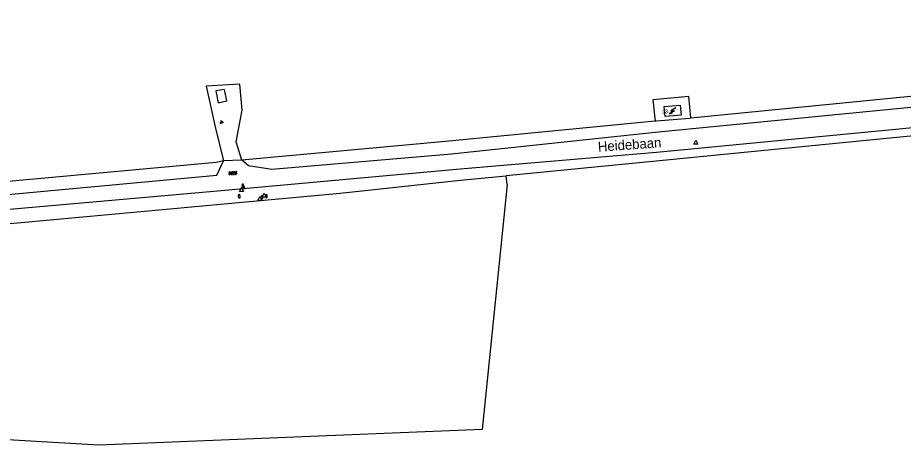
# Model space of a CAD drawing. Extents: x 126000 to 131009, y 393000 to 395500.
# Drawn here: x 127601.7 to 127827.3, y 394615 to 394723.9 of the extents above; entities that cross this region are included whole.
import ezdxf

# ---------------------------------------------------------------- set-up
doc = ezdxf.new("R2010")
doc.units = 0
for name, color, linetype in [('gg-afsc-draadraster', 7, 'Continuous'), ('gg-afsc-faunaraster', 7, 'Continuous'), ('gg-afsc-hekwerk', 7, 'Continuous'), ('gg-anno-huisnummerreeks BGT', 7, 'Continuous'), ('gg-anno-openbare ruimte label', 7, 'Continuous'), ('gg-bbg-hoofdgebouw', 7, 'Continuous'), ('gg-knt-onverhard', 7, 'Continuous'), ('gg-kwrk-betonelement', 7, 'Continuous'), ('gt-grn-groengrens', 7, 'Continuous'), ('gt-symb-brandkraan', 7, 'Continuous'), ('gt-symb-groenvak', 7, 'Continuous'), ('gt-symb-overige verharding', 7, 'Continuous'), ('gt-symb-trafo symbool', 7, 'Continuous'), ('gt-symb-waterafsluiter', 7, 'Continuous')]:
    doc.layers.add(name, color=color, linetype=linetype)

# ---------------------------------------------------------------- blocks, each defined once
blk = doc.blocks.new('gt0-WAFSL')
at = {"layer": 'gt-symb-waterafsluiter'}
for p, q in [((-0.5, -0.33), (0, 0.67)), ((0, 0.67), (0.5, -0.33)), ((0.5, -0.33), (-0.5, -0.33))]:
    blk.add_line(p, q, dxfattribs=at)
blk = doc.blocks.new('gt0-HSP')
at = {"layer": 'gt-symb-trafo symbool'}
for points in [[(0.77, 0.75), (-0.53, 0), (0.47, 0), (-0.83, -0.75)], [(-0.22, -0.24), (-0.83, -0.75), (-0.08, -0.48)]]:
    blk.add_lwpolyline(points, dxfattribs=at)
blk = doc.blocks.new('gt0-BR')
at = {"layer": 'gt-symb-brandkraan'}
for centre, radius, start, end in [((-0.24, 0), 0.206, 107.5669, 252.4331), ((0.6, -2.66), 3, 106.892, 107.5669), ((0, -0.69), 0.938, 73.108, 106.892), ((-0.6, -2.66), 3, 72.4331, 73.108), ((0.24, 0), 0.206, 287.567, 72.4331), ((0.6, 2.66), 3, 252.4331, 253.108), ((0, 0.69), 0.938, 253.108, 286.8921), ((-0.6, 2.66), 3, 286.8921, 287.567)]:
    blk.add_arc(centre, radius, start, end, dxfattribs=at)
blk = doc.blocks.new('gt0-OVH')
at = {"layer": 'gt-symb-overige verharding'}
for points in [[(-0.97, 0.3), (-0.97, 0.31), (-0.96, 0.32), (-0.97, 0.33), (-0.97, 0.34), (-0.98, 0.35), (-0.99, 0.35), (-1, 0.36), (-1.01, 0.35), (-1.02, 0.35), (-1.03, 0.34), (-1.03, 0.33), (-1.04, 0.32), (-1.03, 0.31), (-1.03, 0.3), (-1.02, 0.29), (-1.01, 0.29), (-1, 0.28), (-0.99, 0.29), (-0.98, 0.29)], [(-0.87, 0.11), (-0.87, 0.12), (-0.86, 0.13), (-0.87, 0.14), (-0.87, 0.15), (-0.88, 0.16), (-0.89, 0.16), (-0.9, 0.16), (-0.91, 0.16), (-0.92, 0.16), (-0.93, 0.15), (-0.93, 0.14), (-0.94, 0.13), (-0.93, 0.12), (-0.93, 0.11), (-0.92, 0.1), (-0.91, 0.09), (-0.9, 0.09), (-0.89, 0.09), (-0.88, 0.1)], [(-0.77, 0.3), (-0.77, 0.31), (-0.76, 0.32), (-0.77, 0.33), (-0.77, 0.34), (-0.78, 0.35), (-0.79, 0.35), (-0.8, 0.36), (-0.81, 0.35), (-0.82, 0.35), (-0.83, 0.34), (-0.83, 0.33), (-0.84, 0.32), (-0.83, 0.31), (-0.83, 0.3), (-0.82, 0.29), (-0.81, 0.29), (-0.8, 0.28), (-0.79, 0.29), (-0.78, 0.29)], [(-0.67, 0.11), (-0.67, 0.12), (-0.66, 0.13), (-0.67, 0.14), (-0.67, 0.15), (-0.68, 0.16), (-0.69, 0.16), (-0.7, 0.16), (-0.71, 0.16), (-0.72, 0.16), (-0.73, 0.15), (-0.73, 0.14), (-0.74, 0.13), (-0.73, 0.12), (-0.73, 0.11), (-0.72, 0.1), (-0.71, 0.09), (-0.7, 0.09), (-0.69, 0.09), (-0.68, 0.1)], [(-0.57, 0.3), (-0.57, 0.31), (-0.56, 0.32), (-0.57, 0.33), (-0.57, 0.34), (-0.58, 0.35), (-0.59, 0.35), (-0.6, 0.36), (-0.61, 0.35), (-0.62, 0.35), (-0.63, 0.34), (-0.63, 0.33), (-0.64, 0.32), (-0.63, 0.31), (-0.63, 0.3), (-0.62, 0.29), (-0.61, 0.29), (-0.6, 0.28), (-0.59, 0.29), (-0.58, 0.29)], [(-0.47, 0.11), (-0.47, 0.12), (-0.46, 0.13), (-0.47, 0.14), (-0.47, 0.15), (-0.48, 0.16), (-0.49, 0.16), (-0.5, 0.16), (-0.51, 0.16), (-0.52, 0.16), (-0.53, 0.15), (-0.53, 0.14), (-0.54, 0.13), (-0.53, 0.12), (-0.53, 0.11), (-0.52, 0.1), (-0.51, 0.09), (-0.5, 0.09), (-0.49, 0.09), (-0.48, 0.1)], [(-0.37, 0.3), (-0.37, 0.31), (-0.36, 0.32), (-0.37, 0.33), (-0.37, 0.34), (-0.38, 0.35), (-0.39, 0.35), (-0.4, 0.36), (-0.41, 0.35), (-0.42, 0.35), (-0.43, 0.34), (-0.43, 0.33), (-0.44, 0.32), (-0.43, 0.31), (-0.43, 0.3), (-0.42, 0.29), (-0.41, 0.29), (-0.4, 0.28), (-0.39, 0.29), (-0.38, 0.29)], [(-0.27, 0.11), (-0.27, 0.12), (-0.26, 0.13), (-0.27, 0.14), (-0.27, 0.15), (-0.28, 0.16), (-0.29, 0.16), (-0.3, 0.16), (-0.31, 0.16), (-0.32, 0.16), (-0.33, 0.15), (-0.33, 0.14), (-0.34, 0.13), (-0.33, 0.12), (-0.33, 0.11), (-0.32, 0.1), (-0.31, 0.09), (-0.3, 0.09), (-0.29, 0.09), (-0.28, 0.1)], [(-0.17, 0.3), (-0.17, 0.31), (-0.16, 0.32), (-0.17, 0.33), (-0.17, 0.34), (-0.18, 0.35), (-0.19, 0.35), (-0.2, 0.36), (-0.21, 0.35), (-0.22, 0.35), (-0.23, 0.34), (-0.23, 0.33), (-0.24, 0.32), (-0.23, 0.31), (-0.23, 0.3), (-0.22, 0.29), (-0.21, 0.29), (-0.2, 0.28), (-0.19, 0.29), (-0.18, 0.29)], [(-0.07, 0.11), (-0.07, 0.12), (-0.06, 0.13), (-0.07, 0.14), (-0.07, 0.15), (-0.08, 0.16), (-0.09, 0.16), (-0.1, 0.16), (-0.11, 0.16), (-0.12, 0.16), (-0.13, 0.15), (-0.13, 0.14), (-0.14, 0.13), (-0.13, 0.12), (-0.13, 0.11), (-0.12, 0.1), (-0.11, 0.09), (-0.1, 0.09), (-0.09, 0.09), (-0.08, 0.1)], [(0.03, 0.3), (0.03, 0.31), (0.04, 0.32), (0.03, 0.33), (0.03, 0.34), (0.02, 0.35), (0.01, 0.35), (0, 0.36), (-0.01, 0.35), (-0.02, 0.35), (-0.03, 0.34), (-0.03, 0.33), (-0.04, 0.32), (-0.03, 0.31), (-0.03, 0.3), (-0.02, 0.29), (-0.01, 0.29), (0, 0.28), (0.01, 0.29), (0.02, 0.29)], [(0.13, 0.11), (0.13, 0.12), (0.14, 0.13), (0.13, 0.14), (0.13, 0.15), (0.12, 0.16), (0.11, 0.16), (0.1, 0.16), (0.09, 0.16), (0.08, 0.16), (0.07, 0.15), (0.07, 0.14), (0.06, 0.13), (0.07, 0.12), (0.07, 0.11), (0.08, 0.1), (0.09, 0.09), (0.1, 0.09), (0.11, 0.09), (0.12, 0.1)], [(0.23, 0.3), (0.23, 0.31), (0.24, 0.32), (0.23, 0.33), (0.23, 0.34), (0.22, 0.35), (0.21, 0.35), (0.2, 0.36), (0.19, 0.35), (0.18, 0.35), (0.17, 0.34), (0.17, 0.33), (0.16, 0.32), (0.17, 0.31), (0.17, 0.3), (0.18, 0.29), (0.19, 0.29), (0.2, 0.28), (0.21, 0.29), (0.22, 0.29)], [(0.33, 0.11), (0.33, 0.12), (0.34, 0.13), (0.33, 0.14), (0.33, 0.15), (0.32, 0.16), (0.31, 0.16), (0.3, 0.16), (0.29, 0.16), (0.28, 0.16), (0.27, 0.15), (0.27, 0.14), (0.26, 0.13), (0.27, 0.12), (0.27, 0.11), (0.28, 0.1), (0.29, 0.09), (0.3, 0.09), (0.31, 0.09), (0.32, 0.1)], [(0.43, 0.3), (0.43, 0.31), (0.44, 0.32), (0.43, 0.33), (0.43, 0.34), (0.42, 0.35), (0.41, 0.35), (0.4, 0.36), (0.39, 0.35), (0.38, 0.35), (0.37, 0.34), (0.37, 0.33), (0.36, 0.32), (0.37, 0.31), (0.37, 0.3), (0.38, 0.29), (0.39, 0.29), (0.4, 0.28), (0.41, 0.29), (0.42, 0.29)], [(0.53, 0.11), (0.53, 0.12), (0.54, 0.13), (0.53, 0.14), (0.53, 0.15), (0.52, 0.16), (0.51, 0.16), (0.5, 0.16), (0.49, 0.16), (0.48, 0.16), (0.47, 0.15), (0.47, 0.14), (0.46, 0.13), (0.47, 0.12), (0.47, 0.11), (0.48, 0.1), (0.49, 0.09), (0.5, 0.09), (0.51, 0.09), (0.52, 0.1)], [(0.63, 0.3), (0.63, 0.31), (0.64, 0.32), (0.63, 0.33), (0.63, 0.34), (0.62, 0.35), (0.61, 0.35), (0.6, 0.36), (0.59, 0.35), (0.58, 0.35), (0.57, 0.34), (0.57, 0.33), (0.56, 0.32), (0.57, 0.31), (0.57, 0.3), (0.58, 0.29), (0.59, 0.29), (0.6, 0.28), (0.61, 0.29), (0.62, 0.29)], [(0.73, 0.11), (0.73, 0.12), (0.74, 0.13), (0.73, 0.14), (0.73, 0.15), (0.72, 0.16), (0.71, 0.16), (0.7, 0.16), (0.69, 0.16), (0.68, 0.16), (0.67, 0.15), (0.67, 0.14), (0.66, 0.13), (0.67, 0.12), (0.67, 0.11), (0.68, 0.1), (0.69, 0.09), (0.7, 0.09), (0.71, 0.09), (0.72, 0.1)], [(0.83, 0.3), (0.83, 0.31), (0.84, 0.32), (0.83, 0.33), (0.83, 0.34), (0.82, 0.35), (0.81, 0.35), (0.8, 0.36), (0.79, 0.35), (0.78, 0.35), (0.77, 0.34), (0.77, 0.33), (0.76, 0.32), (0.77, 0.31), (0.77, 0.3), (0.78, 0.29), (0.79, 0.29), (0.8, 0.28), (0.81, 0.29), (0.82, 0.29)], [(0.93, 0.11), (0.93, 0.12), (0.94, 0.13), (0.93, 0.14), (0.93, 0.15), (0.92, 0.16), (0.91, 0.16), (0.9, 0.16), (0.89, 0.16), (0.88, 0.16), (0.87, 0.15), (0.87, 0.14), (0.86, 0.13), (0.87, 0.12), (0.87, 0.11), (0.88, 0.1), (0.89, 0.09), (0.9, 0.09), (0.91, 0.09), (0.92, 0.1)], [(1.03, 0.3), (1.03, 0.31), (1.04, 0.32), (1.03, 0.33), (1.03, 0.34), (1.02, 0.35), (1.01, 0.35), (1, 0.36), (0.99, 0.35), (0.98, 0.35), (0.97, 0.34), (0.97, 0.33), (0.96, 0.32), (0.97, 0.31), (0.97, 0.3), (0.98, 0.29), (0.99, 0.29), (1, 0.28), (1.01, 0.29), (1.02, 0.29)], [(-0.97, -0.14), (-0.97, -0.13), (-0.96, -0.12), (-0.97, -0.11), (-0.97, -0.1), (-0.98, -0.09), (-0.99, -0.09), (-1, -0.08), (-1.01, -0.09), (-1.02, -0.09), (-1.03, -0.1), (-1.03, -0.11), (-1.04, -0.12), (-1.03, -0.13), (-1.03, -0.14), (-1.02, -0.15), (-1.01, -0.15), (-1, -0.16), (-0.99, -0.15), (-0.98, -0.15)], [(-0.87, -0.33), (-0.87, -0.32), (-0.86, -0.31), (-0.87, -0.3), (-0.87, -0.29), (-0.88, -0.28), (-0.89, -0.28), (-0.9, -0.28), (-0.91, -0.28), (-0.92, -0.28), (-0.93, -0.29), (-0.93, -0.3), (-0.94, -0.31), (-0.93, -0.32), (-0.93, -0.33), (-0.92, -0.34), (-0.91, -0.35), (-0.9, -0.35), (-0.89, -0.35), (-0.88, -0.34)], [(-0.77, -0.14), (-0.77, -0.13), (-0.76, -0.12), (-0.77, -0.11), (-0.77, -0.1), (-0.78, -0.09), (-0.79, -0.09), (-0.8, -0.08), (-0.81, -0.09), (-0.82, -0.09), (-0.83, -0.1), (-0.83, -0.11), (-0.84, -0.12), (-0.83, -0.13), (-0.83, -0.14), (-0.82, -0.15), (-0.81, -0.15), (-0.8, -0.16), (-0.79, -0.15), (-0.78, -0.15)], [(-0.67, -0.33), (-0.67, -0.32), (-0.66, -0.31), (-0.67, -0.3), (-0.67, -0.29), (-0.68, -0.28), (-0.69, -0.28), (-0.7, -0.28), (-0.71, -0.28), (-0.72, -0.28), (-0.73, -0.29), (-0.73, -0.3), (-0.74, -0.31), (-0.73, -0.32), (-0.73, -0.33), (-0.72, -0.34), (-0.71, -0.35), (-0.7, -0.35), (-0.69, -0.35), (-0.68, -0.34)], [(-0.57, -0.14), (-0.57, -0.13), (-0.56, -0.12), (-0.57, -0.11), (-0.57, -0.1), (-0.58, -0.09), (-0.59, -0.09), (-0.6, -0.08), (-0.61, -0.09), (-0.62, -0.09), (-0.63, -0.1), (-0.63, -0.11), (-0.64, -0.12), (-0.63, -0.13), (-0.63, -0.14), (-0.62, -0.15), (-0.61, -0.15), (-0.6, -0.16), (-0.59, -0.15), (-0.58, -0.15)], [(-0.47, -0.33), (-0.47, -0.32), (-0.46, -0.31), (-0.47, -0.3), (-0.47, -0.29), (-0.48, -0.28), (-0.49, -0.28), (-0.5, -0.28), (-0.51, -0.28), (-0.52, -0.28), (-0.53, -0.29), (-0.53, -0.3), (-0.54, -0.31), (-0.53, -0.32), (-0.53, -0.33), (-0.52, -0.34), (-0.51, -0.35), (-0.5, -0.35), (-0.49, -0.35), (-0.48, -0.34)], [(-0.37, -0.14), (-0.37, -0.13), (-0.36, -0.12), (-0.37, -0.11), (-0.37, -0.1), (-0.38, -0.09), (-0.39, -0.09), (-0.4, -0.08), (-0.41, -0.09), (-0.42, -0.09), (-0.43, -0.1), (-0.43, -0.11), (-0.44, -0.12), (-0.43, -0.13), (-0.43, -0.14), (-0.42, -0.15), (-0.41, -0.15), (-0.4, -0.16), (-0.39, -0.15), (-0.38, -0.15)], [(-0.27, -0.33), (-0.27, -0.32), (-0.26, -0.31), (-0.27, -0.3), (-0.27, -0.29), (-0.28, -0.28), (-0.29, -0.28), (-0.3, -0.28), (-0.31, -0.28), (-0.32, -0.28), (-0.33, -0.29), (-0.33, -0.3), (-0.34, -0.31), (-0.33, -0.32), (-0.33, -0.33), (-0.32, -0.34), (-0.31, -0.35), (-0.3, -0.35), (-0.29, -0.35), (-0.28, -0.34)], [(-0.17, -0.14), (-0.17, -0.13), (-0.16, -0.12), (-0.17, -0.11), (-0.17, -0.1), (-0.18, -0.09), (-0.19, -0.09), (-0.2, -0.08), (-0.21, -0.09), (-0.22, -0.09), (-0.23, -0.1), (-0.23, -0.11), (-0.24, -0.12), (-0.23, -0.13), (-0.23, -0.14), (-0.22, -0.15), (-0.21, -0.15), (-0.2, -0.16), (-0.19, -0.15), (-0.18, -0.15)], [(-0.07, -0.33), (-0.07, -0.32), (-0.06, -0.31), (-0.07, -0.3), (-0.07, -0.29), (-0.08, -0.28), (-0.09, -0.28), (-0.1, -0.28), (-0.11, -0.28), (-0.12, -0.28), (-0.13, -0.29), (-0.13, -0.3), (-0.14, -0.31), (-0.13, -0.32), (-0.13, -0.33), (-0.12, -0.34), (-0.11, -0.35), (-0.1, -0.35), (-0.09, -0.35), (-0.08, -0.34)], [(0.03, -0.14), (0.03, -0.13), (0.04, -0.12), (0.03, -0.11), (0.03, -0.1), (0.02, -0.09), (0.01, -0.09), (0, -0.08), (-0.01, -0.09), (-0.02, -0.09), (-0.03, -0.1), (-0.03, -0.11), (-0.04, -0.12), (-0.03, -0.13), (-0.03, -0.14), (-0.02, -0.15), (-0.01, -0.15), (0, -0.16), (0.01, -0.15), (0.02, -0.15)], [(0.13, -0.33), (0.13, -0.32), (0.14, -0.31), (0.13, -0.3), (0.13, -0.29), (0.12, -0.28), (0.11, -0.28), (0.1, -0.28), (0.09, -0.28), (0.08, -0.28), (0.07, -0.29), (0.07, -0.3), (0.06, -0.31), (0.07, -0.32), (0.07, -0.33), (0.08, -0.34), (0.09, -0.35), (0.1, -0.35), (0.11, -0.35), (0.12, -0.34)], [(0.23, -0.14), (0.23, -0.13), (0.24, -0.12), (0.23, -0.11), (0.23, -0.1), (0.22, -0.09), (0.21, -0.09), (0.2, -0.08), (0.19, -0.09), (0.18, -0.09), (0.17, -0.1), (0.17, -0.11), (0.16, -0.12), (0.17, -0.13), (0.17, -0.14), (0.18, -0.15), (0.19, -0.15), (0.2, -0.16), (0.21, -0.15), (0.22, -0.15)], [(0.33, -0.33), (0.33, -0.32), (0.34, -0.31), (0.33, -0.3), (0.33, -0.29), (0.32, -0.28), (0.31, -0.28), (0.3, -0.28), (0.29, -0.28), (0.28, -0.28), (0.27, -0.29), (0.27, -0.3), (0.26, -0.31), (0.27, -0.32), (0.27, -0.33), (0.28, -0.34), (0.29, -0.35), (0.3, -0.35), (0.31, -0.35), (0.32, -0.34)], [(0.43, -0.14), (0.43, -0.13), (0.44, -0.12), (0.43, -0.11), (0.43, -0.1), (0.42, -0.09), (0.41, -0.09), (0.4, -0.08), (0.39, -0.09), (0.38, -0.09), (0.37, -0.1), (0.37, -0.11), (0.36, -0.12), (0.37, -0.13), (0.37, -0.14), (0.38, -0.15), (0.39, -0.15), (0.4, -0.16), (0.41, -0.15), (0.42, -0.15)], [(0.53, -0.33), (0.53, -0.32), (0.54, -0.31), (0.53, -0.3), (0.53, -0.29), (0.52, -0.28), (0.51, -0.28), (0.5, -0.28), (0.49, -0.28), (0.48, -0.28), (0.47, -0.29), (0.47, -0.3), (0.46, -0.31), (0.47, -0.32), (0.47, -0.33), (0.48, -0.34), (0.49, -0.35), (0.5, -0.35), (0.51, -0.35), (0.52, -0.34)], [(0.63, -0.14), (0.63, -0.13), (0.64, -0.12), (0.63, -0.11), (0.63, -0.1), (0.62, -0.09), (0.61, -0.09), (0.6, -0.08), (0.59, -0.09), (0.58, -0.09), (0.57, -0.1), (0.57, -0.11), (0.56, -0.12), (0.57, -0.13), (0.57, -0.14), (0.58, -0.15), (0.59, -0.15), (0.6, -0.16), (0.61, -0.15), (0.62, -0.15)], [(0.73, -0.33), (0.73, -0.32), (0.74, -0.31), (0.73, -0.3), (0.73, -0.29), (0.72, -0.28), (0.71, -0.28), (0.7, -0.28), (0.69, -0.28), (0.68, -0.28), (0.67, -0.29), (0.67, -0.3), (0.66, -0.31), (0.67, -0.32), (0.67, -0.33), (0.68, -0.34), (0.69, -0.35), (0.7, -0.35), (0.71, -0.35), (0.72, -0.34)], [(0.83, -0.14), (0.83, -0.13), (0.84, -0.12), (0.83, -0.11), (0.83, -0.1), (0.82, -0.09), (0.81, -0.09), (0.8, -0.08), (0.79, -0.09), (0.78, -0.09), (0.77, -0.1), (0.77, -0.11), (0.76, -0.12), (0.77, -0.13), (0.77, -0.14), (0.78, -0.15), (0.79, -0.15), (0.8, -0.16), (0.81, -0.15), (0.82, -0.15)], [(0.93, -0.33), (0.93, -0.32), (0.94, -0.31), (0.93, -0.3), (0.93, -0.29), (0.92, -0.28), (0.91, -0.28), (0.9, -0.28), (0.89, -0.28), (0.88, -0.28), (0.87, -0.29), (0.87, -0.3), (0.86, -0.31), (0.87, -0.32), (0.87, -0.33), (0.88, -0.34), (0.89, -0.35), (0.9, -0.35), (0.91, -0.35), (0.92, -0.34)], [(1.03, -0.14), (1.03, -0.13), (1.04, -0.12), (1.03, -0.11), (1.03, -0.1), (1.02, -0.09), (1.01, -0.09), (1, -0.08), (0.99, -0.09), (0.98, -0.09), (0.97, -0.1), (0.97, -0.11), (0.96, -0.12), (0.97, -0.13), (0.97, -0.14), (0.98, -0.15), (0.99, -0.15), (1, -0.16), (1.01, -0.15), (1.02, -0.15)]]:
    blk.add_lwpolyline(points, close=True, dxfattribs=at)
blk = doc.blocks.new('gt0-GRVAK')
at = {"layer": 'gt-symb-groenvak'}
for p, q in [((-0.11, 0.19), (-0.23, 0.24)), ((-0.18, 0.15), (0.09, 0.15)), ((-0.09, 0.21), (-0.16, 0.32)), ((-0.05, 0.21), (-0.05, 0.39)), ((0, 0.21), (0.06, 0.32)), ((0.01, 0.19), (0.13, 0.24)), ((0.26, -0.05), (0.2, 0.06)), ((0.3, -0.05), (0.3, 0.13)), ((0.35, -0.05), (0.41, 0.06)), ((-0.25, -0.23), (-0.36, -0.18)), ((-0.32, -0.26), (-0.05, -0.26)), ((-0.23, -0.21), (-0.29, -0.1)), ((-0.18, -0.2), (-0.18, -0.02)), ((-0.14, -0.21), (-0.07, -0.1)), ((-0.12, -0.23), (0, -0.18)), ((0.24, -0.07), (0.12, -0.02)), ((0.17, -0.11), (0.44, -0.11)), ((0.37, -0.07), (0.49, -0.02))]:
    blk.add_line(p, q, dxfattribs=at)

msp = doc.modelspace()

# ---------------------------------------------------------------- linework, layer by layer
at = {"layer": 'gg-afsc-draadraster'}
for p, q in [((127764.09, 394697.58), (127764.43, 394697.65)), ((127772.91, 394698.33), (127773.23, 394698.39))]:
    msp.add_line(p, q, dxfattribs=at)
for points in [[(127773.23, 394698.39), (127836.91, 394704.71), (127865.56, 394707.32)], [(127773.23, 394698.39), (127772.69, 394703.86), (127763.55, 394702.96), (127764.09, 394697.58)], [(127764.09, 394697.58), (127710.69, 394692.41), (127658.84, 394687.6)], [(127654.16, 394687.44), (127652.28, 394687.04), (127418.99, 394665.72)]]:
    msp.add_lwpolyline(points, dxfattribs=at)
at = {"layer": 'gg-afsc-faunaraster'}
for points in [[(127881.65, 394698.5), (127879.62, 394698.35), (127836.05, 394694.39), (127764.42, 394687.37), (127726.17, 394683.66)], [(127565.57, 394668.35), (127683.84, 394679.24), (127714.5, 394682.53), (127726.17, 394683.66)]]:
    msp.add_lwpolyline(points, dxfattribs=at)
at = {"layer": 'gg-afsc-hekwerk'}
msp.add_line((127764.43, 394697.65), (127772.91, 394698.33), dxfattribs=at)
at = {"layer": 'gg-bbg-hoofdgebouw'}
msp.add_lwpolyline([(127766.68, 394698.74), (127766.43, 394701.26), (127770.49, 394701.64), (127770.75, 394699.12), (127766.68, 394698.74)], dxfattribs=at)
at = {"layer": 'gg-knt-onverhard'}
msp.add_line((127658.84, 394687.6), (127654.16, 394687.44), dxfattribs=at)
for points in [[(127428.11, 394659.32), (127547.52, 394670.55), (127651.63, 394679.7), (127714.41, 394685.42), (127764.46, 394689.67), (127835.99, 394696.53), (127879.48, 394700.8), (127914.73, 394703.79), (127964.79, 394708.41), (127994.45, 394710.57), (128018.1, 394714.01), (128037.11, 394715.04), (128095.15, 394719.63), (128135.3, 394722.62), (128140.76, 394722.95), (128145.28, 394723.9)], [(127879.76, 394704.89), (127836.11, 394701.74), (127764.12, 394694.65), (127712.2, 394689.17), (127666.42, 394685.23), (127660.46, 394686.16), (127658.84, 394687.6)], [(127422.93, 394661.18), (127546.82, 394674.02), (127652.4, 394683.84), (127654.16, 394687.44)]]:
    msp.add_lwpolyline(points, dxfattribs=at)
at = {"layer": 'gg-kwrk-betonelement'}
msp.add_lwpolyline([(127654.36, 394705.66), (127652.18, 394705.3), (127652.79, 394702.26), (127654.94, 394702.71), (127654.36, 394705.66)], dxfattribs=at)
at = {"layer": 'gt-grn-groengrens'}
msp.add_line((127726.39, 394681.44), (127726.17, 394683.66), dxfattribs=at)
for points in [[(127658.84, 394687.6), (127657.38, 394692.28), (127658.86, 394700.37), (127658.29, 394706.96), (127649.69, 394706.43), (127651.97, 394696.13), (127654.16, 394687.44)], [(127726.39, 394681.44), (127720.05, 394619.06), (127622.4, 394615), (127562.8, 394618.55), (127565.69, 394666.99)]]:
    msp.add_lwpolyline(points, dxfattribs=at)

# ---------------------------------------------------------------- block references
at = {"layer": 'gt-symb-brandkraan'}
for p, rotation in [((127659.08, 394681.08), 94.53981548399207), ((127658.12, 394678.43), 94.53981548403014), ((127663.96, 394678.15), 94.53981548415), ((127665.05, 394678.4), 94.53981548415)]:
    msp.add_blockref('gt0-BR', p, dxfattribs=dict(at, rotation=rotation))
at = {"layer": 'gt-symb-groenvak'}
msp.add_blockref('gt0-GRVAK', (127653.63, 394697.32), dxfattribs=at)
at = {"layer": 'gt-symb-overige verharding', "rotation": 3.1543921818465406}
msp.add_blockref('gt0-OVH', (127656.51, 394684.3), dxfattribs=at)
at = {"layer": 'gt-symb-trafo symbool'}
msp.add_blockref('gt0-HSP', (127768.61, 394700.19), dxfattribs=at)
at = {"layer": 'gt-symb-waterafsluiter'}
for p in [(127774.51, 394692.01), (127659.18, 394680.64), (127658.74, 394679.96), (127664.46, 394678.51), (127663.39, 394677.67)]:
    msp.add_blockref('gt0-WAFSL', p, dxfattribs=at)

# ---------------------------------------------------------------- texts
at = {"layer": 'gg-anno-huisnummerreeks BGT'}
msp.add_text('23', height=1, rotation=5.9, dxfattribs=at).set_placement((127765.92, 394699.43))
at = {"layer": 'gg-anno-openbare ruimte label'}
msp.add_text('Heidebaan', height=2.5, rotation=4.1, dxfattribs=at).set_placement((127749.63, 394689.76))

doc.saveas('drawing.dxf')
